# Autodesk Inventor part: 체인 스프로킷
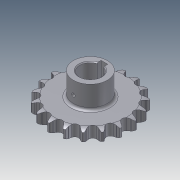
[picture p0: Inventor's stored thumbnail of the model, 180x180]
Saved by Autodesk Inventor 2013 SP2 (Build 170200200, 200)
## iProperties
Created: 2014-07
Part Number: 체인 스프로킷
Material: 강
Document SubType Name: Modeling
Designer: KYOUNG IL JANG
Density: 7.85 g/cm^3
Mass: 738.6 g
Surface Area: 236.854 cm^2
Volume: 94.0892 cm^3
CustomPartVersion: 1
Company: 한국ATC센터
Author: KYOUNG IL JANG
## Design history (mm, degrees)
sketch "이론적 톱니 프로파일"
  geometry: L1 (0, 0)-(0, 45.567); L2 (0, 0)-(14.795, 43.098); L3 (0, 45.567)-(14.795, 43.098); L4 (0, 45.567)-(5.661, 50.015); L5 (5.661, 50.015)-(-5.141, 45.406); L6 (-12.428, 43.493)-(-5.573, 46.417); L7 (-5.141, 45.406)-(-5.573, 46.417); L8 (5.573, 46.417)-(5.141, 45.406); L9 (0, 0)-(8.138, 48.771); A1 r 45.567 centre (0, 0) between (0, 45.567) and (14.795, 43.098); A2 r 49.445 centre (0, 0) between (7.302, 48.903) and (-7.302, 48.903); A3 r 4.545 centre (0, 45.567) between (-3.574, 42.758) and (3.574, 42.758); A4 r 7.453 centre (12.428, 43.493) between (7.302, 48.903) and (5.573, 46.417); A5 r 7.453 centre (-12.428, 43.493) between (-5.573, 46.417) and (-7.302, 48.903); A6 r 11.745 centre (5.661, 50.015) between (-5.141, 45.406) and (-3.574, 42.758); A7 r 11.745 centre (-5.661, 50.015) between (3.574, 42.758) and (5.141, 45.406); 2 further points
  constraints: 18 end point, 15 point on circle, 7 centre point, 3 coincident, 3 point on line, 3 symmetric about line, 3 tangent, 1 equal radius, 1 midpoint, 1 parallel, 1 vertical, 1 other
  dimensions: "d0" = 91.13301 diameter of A1 (computed from da_p, da_z); "d2" = 18.9474 deg angle of L2 L1 (computed from da_z); "d3" = 4.545 radius of A3 (= 0.5 x da_Dr + da_SC); "d10" = 128.158 deg angle of L4 L1 (computed from da_z); "d11" = 15.0526 deg angle of L5 L4 (computed from da_z); "d12" = 7.2 distance of L3.start L4.end (= 0.8 x da_Dr); "d13" = 11.745 distance of L4.end L5.end (= 1.3 x da_Dr + da_SC); "d14" = 12.6 distance of A4.centre L1.end (= 1.4 x da_Dr); "d23" = 4.5 distance from line of L9.end L3 (= da_Ha)
sketch "톱니 프로파일"
  geometry: L1 (0, 0)-(0, 45.567); L2 (0, 45.567)-(4.203, 43.837); L3 (0, 45.567)-(-4.203, 43.837); A1 r 4.545 centre (0, 45.567) between (-4.203, 43.837) and (4.203, 43.837); A2 r 22.68 centre (25.176, 35.206) between (7.12, 48.93) and (4.203, 43.837); A3 r 22.68 centre (-25.176, 35.206) between (-4.203, 43.837) and (-7.12, 48.93); A4 r 49.445 centre (0, 0) between (-7.12, 48.93) and (7.12, 48.93) reference; 1 further point
  constraints: 9 point on circle, 6 end point, 3 centre point, 2 tangent, 1 coincident, 1 equal radius, 1 vertical, 1 other
  dimensions: "d44" = 135.263 deg angle of L3 L2 (= da_Alfa); "d45" = 22.68 radius of A2 (= da_Re); "d46" = 4.545 radius of A1 (= da_Ri)
sketch "단면 프로파일"
  geometry: L1 (49.445, 0)-(-49.445, 0) reference; L2 (33.265, 6.65)-(-33.265, 6.65); L3 (-33.265, 6.65)-(-33.265, -6.65); L4 (-33.265, -6.65)-(33.265, -6.65); L5 (33.265, -6.65)-(33.265, 6.65); L6 (33.265, 6.65)-(49.445, 6.65); L7 (49.445, 6.65)-(49.445, -6.65); L8 (49.445, -6.65)-(33.265, -6.65); L9 (33.265, -6.65)-(33.265, 6.65); L10 (42.183, 6.65)-(0, 6.65); L11 (0, 6.65)-(0, -6.65); L12 (0, -6.65)-(42.183, -6.65); L13 (0, 6.65)-(0, -6.65); L14 (49.445, 4.775)-(49.445, -4.775); A1 r 15 centre (42.183, -8.35) between (49.445, 4.775) and (42.183, 6.65); A2 r 15 centre (42.183, 8.35) between (42.183, -6.65) and (49.445, -4.775); 2 further points
  constraints: 26 end point, 7 midpoint, 5 perpendicular, 4 parallel, 4 point on circle, 3 point on line, 3 symmetric about line, 2 centre point, 2 horizontal, 2 tangent, 1 collinear, 1 other
  dimensions: "d30" = 13.3 distance between parallel lines of L8 L6 (= da_Bf); "d31" = 66.53007 distance between parallel lines of L3 L5 (= da_Ds); "d32" = 13.3 distance between parallel lines of L4 L2 (= da_Bs); "d33" = 1.875 distance from line of L14.start L6 (= da_Ba); "d34" = 15 radius of A1 (= da_Rx); "d43" = 6.65 distance between parallel lines of L4 L1 (computed from da_k, da_pt, da_Bs)
revolve "슈라우드" stored, may be unused: angle "d36" = 90 deg
revolve "스트랜드" stored, may be unused: angle "d37" = 90 deg
extrude "이론적 톱니" cut sketch "이론적 톱니 프로파일" stored distance "d18" = 10; taper "d19" = 0 deg; dims "d49" = 0, "form_type" = 0 [user parameter]
extrude "톱니" cut sketch "톱니 프로파일" stored distance "d47" = 10; taper "d48" = 0 deg; dims "d50" = 10, "form_type" = 0 [user parameter]
node "타이밍 평면"
node "작업 평면3"
sketch "스케치5"
  geometry: C1 r 20 at (0, -45.567); 1 further point
  constraints: 1 centre point, 1 coincident
  dimensions: "d52" = 40 diameter of C1
extrude "돌출4" join sketch "스케치5" stored distance "d53" = 10; taper "d54" = 0 deg
sketch "스케치6"
  geometry: L1 (4, 11.843)-(4, 16.5); L2 (4, 16.5)-(-4, 16.5); L3 (-4, 16.5)-(-4, 11.843); A1 r 12.5 centre (0, 0) between (4, 11.843) and (-4, 11.843); 1 further point
  constraints: 6 end point, 2 parallel, 2 point on circle, 1 centre point, 1 coincident, 1 perpendicular, 1 vertical
  dimensions: "d55" = 25 diameter of A1; "d56" = 29 dimension on A1 L2 (computed from d55); "d57" = 8 distance of L1.end L2.end
extrude "돌출5" cut sketch "스케치6" stored distance "d58" = 10; taper "d59" = 0 deg
fillet "모깎기2" dims "d60" = 3
chamfer "모따기1" distance "d61" = 1; stored, may be unused: second distance "d62" = 2, angle "d63" = 45 deg
node "작업 평면4"
sketch "스케치7"
  geometry: L1 (-13.5, -13.3)-(13.5, -13.3) reference; 4 further points
  constraints: 1 vertical alignment
  dimensions: "d65" = 25 distance from line of point (0, 11.7) L1
hole "구멍1" sketch "스케치7" at (0, 11.7) diameter "d66" = 4.134; stored, may be unused: countersink angle "d70" = 90 deg, drill point angle "d72" = 118 deg; dims "d67" = 6, "d68" = 4, "d69" = 2, "d71" = 8
body "Solid1"
pattern_linear "스트랜드 패턴" dims "d40" = 24 (= da_pt)
pattern_circular "톱니 패턴" dims angle "d21" = 360 deg
other parameters: "da_p" = 15 [user parameter; used in 1 equation term], "da_Dr" = 9 [user parameter; used in 4 equation terms], "da_SC" = 0.045 [user parameter; used in 2 equation terms], "da_Ha" = 4.5 [user parameter; used in 1 equation term], "da_pt" = 24 [user parameter; used in 2 equation terms], "da_Bf" = 13.3 [user parameter; used in 1 equation term], "d28" = 0, "d29" = 0, "da_Ba" = 1.875 [user parameter; used in 1 equation term], "da_Rx" = 15 [user parameter; used in 1 equation term], "da_Ra" = 0.6 [user parameter], "da_Bs" = 13.3 [user parameter; used in 2 equation terms], "da_Ds" = 66.53007 [user parameter; used in 1 equation term], "d42" = 0, "da_Re" = 22.68 [user parameter; used in 1 equation term], "da_Ri" = 4.545 [user parameter; used in 1 equation term], "da_Alfa" = 135.263 deg [user parameter; used in 1 equation term]
